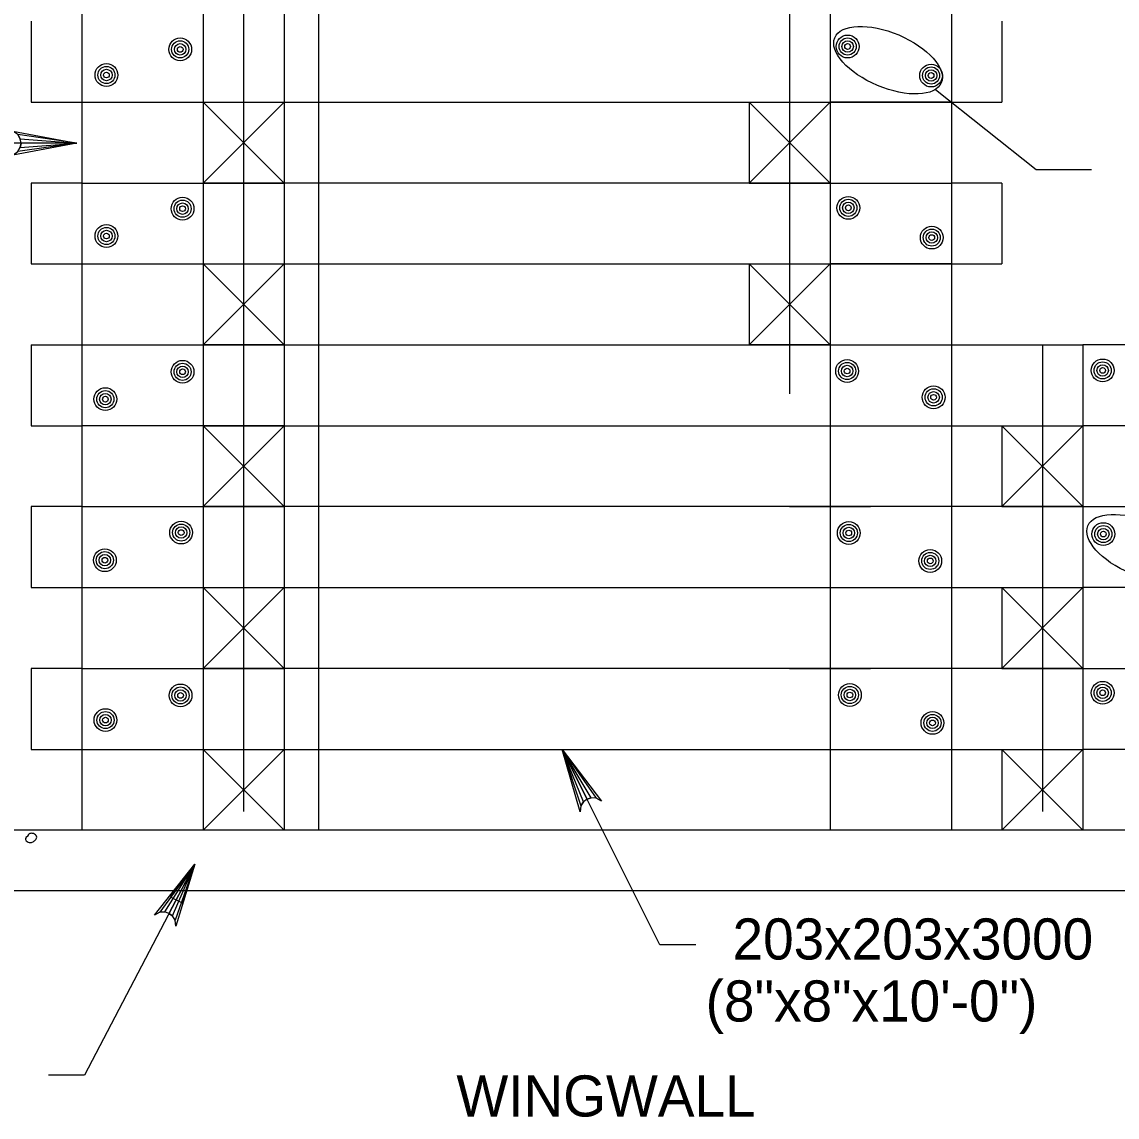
# Model space of a CAD drawing. Extents: x 0 to 36.3, y -44 to 0.
# Drawn here: x 18.454 to 21.652, y -17.836 to -14.638 of the extents above; entities that cross this region are included whole.
import ezdxf

# ---------------------------------------------------------------- set-up
doc = ezdxf.new("R2010")
doc.units = 0
doc.layers.add('3', color=7, linetype='Continuous')
doc.layers.add('5', color=7, linetype='Continuous')

msp = doc.modelspace()

# ---------------------------------------------------------------- linework, layer by layer
at = {"layer": '3'}
for p, q in [((18.6286, -13.9278), (18.6286, -16.9987)), ((19.101, -13.9278), (19.101, -16.9439)), ((19.2192, -13.9278), (19.2192, -16.9987)), ((19.3198, -13.9278), (19.3198, -16.5576)), ((18.9829, -14.1641), (18.9829, -16.9987)), ((20.6955, -14.1641), (20.6955, -15.7248)), ((20.8137, -14.1641), (20.8137, -16.563)), ((21.168, -14.1641), (21.168, -15.8176)), ((21.168, -14.4002), (21.168, -16.9987)), ((18.4809, -14.6365), (18.4809, -14.8727)), ((21.3156, -14.6365), (21.3156, -14.8727)), ((18.4809, -14.8727), (18.6286, -14.8727)), ((18.6286, -14.8727), (18.9829, -14.8727)), ((18.9829, -14.8727), (20.8137, -14.8727)), ((18.9829, -14.8727), (19.2192, -14.8727)), ((18.9829, -14.8727), (18.9829, -15.1089)), ((18.9829, -15.1089), (19.2192, -14.8727)), ((18.9829, -14.8727), (19.2192, -15.1089)), ((19.2192, -14.8727), (19.2192, -15.1089)), ((20.5774, -14.8727), (20.8137, -14.8727)), ((20.5774, -14.8727), (20.8137, -15.1089)), ((20.5774, -15.1089), (20.8137, -14.8727)), ((20.5774, -14.8727), (20.5774, -15.1089)), ((20.8137, -14.8727), (21.168, -14.8727)), ((20.8137, -14.8727), (20.8137, -15.1089)), ((21.168, -14.8727), (20.8137, -14.8727)), ((21.168, -14.8727), (21.3156, -14.8727)), ((18.6286, -15.1089), (18.4809, -15.1089)), ((18.4809, -15.1089), (18.4809, -15.3452)), ((18.6286, -15.1089), (18.9829, -15.1089)), ((18.9829, -15.1089), (19.2192, -15.1089)), ((19.2192, -15.1089), (18.9829, -15.1089)), ((20.8137, -15.1089), (18.9829, -15.1089)), ((20.5774, -15.1089), (20.8137, -15.1089)), ((20.8137, -15.1089), (21.168, -15.1089)), ((21.3156, -15.1089), (21.168, -15.1089)), ((21.3156, -15.1089), (21.3156, -15.3452)), ((18.4809, -15.3452), (18.6286, -15.3452)), ((18.6286, -15.3452), (18.9829, -15.3452)), ((18.9829, -15.3452), (20.8137, -15.3452)), ((18.9829, -15.3452), (19.2192, -15.3452)), ((18.9829, -15.3452), (19.2192, -15.5814)), ((18.9829, -15.5814), (19.2192, -15.3452)), ((18.9829, -15.3452), (18.9829, -15.5814)), ((19.2192, -15.3452), (19.2192, -15.5814)), ((20.5774, -15.3452), (20.8137, -15.3452)), ((20.5774, -15.3452), (20.5774, -15.5814)), ((20.5774, -15.5814), (20.8137, -15.3452)), ((20.5774, -15.3452), (20.8137, -15.5814)), ((20.8137, -15.3452), (20.8137, -15.5814)), ((20.8137, -15.3452), (21.168, -15.3452)), ((21.168, -15.3452), (20.8137, -15.3452)), ((21.168, -15.3452), (21.3156, -15.3452)), ((18.4809, -15.5814), (18.4809, -15.8176)), ((18.4809, -15.5814), (18.6286, -15.5814)), ((18.6286, -15.5814), (18.9829, -15.5814)), ((18.9829, -15.5814), (21.5518, -15.5814)), ((19.2192, -15.5814), (18.9829, -15.5814)), ((18.9829, -15.5814), (19.2192, -15.5814)), ((20.5774, -15.5814), (20.8137, -15.5814)), ((20.8137, -15.5814), (20.5774, -15.5814)), ((21.4337, -15.5814), (21.4337, -16.9439)), ((21.5518, -15.5814), (21.5518, -16.9987)), ((21.9062, -15.5814), (21.5518, -15.5814)), ((18.4809, -15.8176), (18.6286, -15.8176)), ((19.2192, -15.8176), (18.6286, -15.8176)), ((18.9829, -15.8176), (19.2192, -15.8176)), ((18.9829, -15.8176), (18.9829, -16.0538)), ((18.9829, -16.0538), (19.2192, -15.8176)), ((18.9829, -15.8176), (19.2192, -16.0538)), ((19.2192, -15.8176), (19.2192, -16.0538)), ((19.2192, -15.8176), (21.5518, -15.8176)), ((20.6955, -15.8176), (20.9318, -15.8176)), ((21.3156, -15.8176), (21.3156, -16.0538)), ((21.3156, -16.0538), (21.5518, -15.8176)), ((21.3156, -15.8176), (21.5518, -16.0538)), ((21.3156, -15.8176), (21.5518, -15.8176)), ((21.5518, -15.8176), (21.5518, -16.0538)), ((21.9062, -15.8176), (21.5518, -15.8176)), ((18.6286, -16.0538), (18.4809, -16.0538)), ((18.4809, -16.0538), (18.4809, -16.29)), ((18.6286, -16.0538), (18.9829, -16.0538)), ((18.9829, -16.0538), (19.2192, -16.0538)), ((21.5518, -16.0538), (18.9829, -16.0538)), ((20.6955, -16.0538), (20.9318, -16.0538)), ((21.3156, -16.0538), (21.5518, -16.0538)), ((21.5518, -16.0538), (21.9062, -16.0538)), ((18.4809, -16.29), (18.6286, -16.29)), ((18.6286, -16.29), (18.9829, -16.29)), ((18.9829, -16.29), (19.2192, -16.29)), ((18.9829, -16.29), (19.2192, -16.5263)), ((18.9829, -16.5263), (19.2192, -16.29)), ((18.9829, -16.29), (18.9829, -16.5263)), ((18.9829, -16.29), (21.5518, -16.29)), ((19.2192, -16.29), (19.2192, -16.5263)), ((20.6955, -16.29), (20.8137, -16.29)), ((21.3156, -16.29), (21.5518, -16.29)), ((21.3156, -16.29), (21.5518, -16.5263)), ((21.3156, -16.5263), (21.5518, -16.29)), ((21.3156, -16.29), (21.3156, -16.5263)), ((21.5518, -16.29), (21.5518, -16.5263)), ((21.9062, -16.29), (21.5518, -16.29)), ((18.4809, -16.5263), (18.4809, -16.7625)), ((18.6286, -16.5263), (18.4809, -16.5263)), ((18.6286, -16.5263), (18.9829, -16.5263)), ((18.9829, -16.5263), (19.2192, -16.5263)), ((21.5518, -16.5263), (18.9829, -16.5263)), ((20.6955, -16.5263), (20.9318, -16.5263)), ((21.3156, -16.5263), (21.5518, -16.5263)), ((21.5518, -16.5263), (21.9062, -16.5263)), ((19.3198, -16.5576), (19.3198, -16.9987)), ((20.8137, -16.563), (20.8137, -16.9987)), ((18.4809, -16.7625), (18.6286, -16.7625)), ((18.6286, -16.7625), (18.9829, -16.7625)), ((18.9829, -16.7625), (19.2192, -16.7625)), ((18.9829, -16.7625), (21.5518, -16.7625)), ((18.9829, -16.7625), (18.9829, -16.9987)), ((18.9829, -16.9987), (19.2192, -16.7625)), ((18.9829, -16.7625), (19.2192, -16.9987)), ((19.2192, -16.7625), (19.2192, -16.9987)), ((19.5439, -16.7625), (21.4632, -16.7625)), ((21.3156, -16.7625), (21.3156, -16.9987)), ((21.3156, -16.9987), (21.5518, -16.7625)), ((21.3156, -16.7625), (21.5518, -16.9987)), ((21.3156, -16.7625), (21.5518, -16.7625)), ((21.5518, -16.7625), (21.5518, -16.9987)), ((21.9062, -16.7625), (21.5518, -16.7625)), ((22.2309, -16.9987), (18.2742, -16.9987)), ((22.7392, -17.1758), (17.728, -17.1758))]:
    msp.add_line(p, q, dxfattribs=at)
for centre, radius in [((20.865, -14.7102), 0.0333), ((18.916, -14.7186), 0.0333), ((18.916, -14.7186), 0.025), ((18.916, -14.7186), 0.0167), ((18.916, -14.7186), 0.00833), ((20.865, -14.7102), 0.025), ((20.865, -14.7102), 0.0167), ((20.865, -14.7102), 0.00833), ((18.7006, -14.7935), 0.0333), ((18.7006, -14.7935), 0.025), ((21.1087, -14.7949), 0.0333), ((21.1087, -14.7949), 0.025), ((18.7006, -14.7935), 0.0167), ((18.7006, -14.7935), 0.00833), ((21.1087, -14.7949), 0.0167), ((21.1087, -14.7949), 0.00833), ((18.923, -15.1837), 0.0333), ((18.923, -15.1837), 0.025), ((20.8671, -15.1813), 0.0333), ((20.8671, -15.1813), 0.025), ((18.923, -15.1837), 0.0167), ((18.923, -15.1837), 0.00833), ((20.8671, -15.1813), 0.0167), ((20.8671, -15.1813), 0.00833), ((18.7006, -15.2636), 0.0333), ((18.7006, -15.2636), 0.025), ((18.7006, -15.2636), 0.0167), ((21.1107, -15.2681), 0.0333), ((21.1107, -15.2681), 0.025), ((21.1107, -15.2681), 0.0167), ((18.7006, -15.2636), 0.00833), ((21.1107, -15.2681), 0.00833), ((18.923, -15.66), 0.0333), ((18.923, -15.66), 0.025), ((20.8635, -15.6578), 0.0333), ((20.8635, -15.6578), 0.025), ((21.6097, -15.656), 0.0333), ((21.6097, -15.656), 0.025), ((18.923, -15.66), 0.0167), ((18.923, -15.66), 0.00833), ((20.8635, -15.6578), 0.0167), ((20.8635, -15.6578), 0.00833), ((21.6097, -15.656), 0.0167), ((21.6097, -15.656), 0.00833), ((21.1161, -15.7345), 0.0333), ((18.6975, -15.7399), 0.0333), ((18.6975, -15.7399), 0.025), ((18.6975, -15.7399), 0.0167), ((18.6975, -15.7399), 0.00833), ((21.1161, -15.7345), 0.025), ((21.1161, -15.7345), 0.0167), ((21.1161, -15.7345), 0.00833), ((18.9188, -16.1295), 0.0333), ((18.9188, -16.1295), 0.025), ((18.9188, -16.1295), 0.0167), ((20.8684, -16.1307), 0.0333), ((20.8684, -16.1307), 0.025), ((20.8684, -16.1307), 0.0167), ((21.6118, -16.1339), 0.0333), ((21.6118, -16.1339), 0.025), ((21.6118, -16.1339), 0.0167), ((18.9188, -16.1295), 0.00833), ((20.8684, -16.1307), 0.00833), ((21.6118, -16.1339), 0.00833), ((18.6961, -16.2102), 0.0333), ((21.1063, -16.2123), 0.0333), ((18.6961, -16.2102), 0.025), ((18.6961, -16.2102), 0.0167), ((18.6961, -16.2102), 0.00833), ((21.1063, -16.2123), 0.025), ((21.1063, -16.2123), 0.0167), ((21.1063, -16.2123), 0.00833), ((21.6097, -16.5973), 0.0333), ((18.917, -16.605), 0.0333), ((18.917, -16.605), 0.025), ((18.917, -16.605), 0.0167), ((18.917, -16.605), 0.00833), ((20.8716, -16.6037), 0.0333), ((20.8716, -16.6037), 0.025), ((20.8716, -16.6037), 0.0167), ((20.8716, -16.6037), 0.00833), ((21.6097, -16.5973), 0.025), ((21.6097, -16.5973), 0.0167), ((21.6097, -16.5973), 0.00833), ((18.6978, -16.677), 0.0333), ((18.6978, -16.677), 0.025), ((18.6978, -16.677), 0.0167), ((21.1128, -16.6852), 0.0333), ((21.1128, -16.6852), 0.025), ((18.6978, -16.677), 0.00833), ((21.1128, -16.6852), 0.0167), ((21.1128, -16.6852), 0.00833)]:
    msp.add_circle(centre, radius, dxfattribs=at)
for centre, radius, start, end in [((18.4836, -17.0203), 0.014, 140.7081, 167.2711), ((18.4804, -17.0176), 0.00984, 108.9149, 140.7081), ((18.4822, -17.023), 0.0155, 90, 108.9149), ((18.4822, -17.0257), 0.0182, 72.5511, 90), ((18.4831, -17.0229), 0.0153, 47.7288, 72.5511), ((18.4856, -17.0202), 0.0115, 19.08, 47.7288), ((18.4718, -17.0242), 0.00747, 143.9702, 187.7584), ((18.4715, -17.0243), 0.00724, 187.7584, 225.0025), ((18.473, -17.0252), 0.00907, 104.4085, 143.9702), ((18.4787, -17.0171), 0.0173, 225.0025, 248.8171), ((18.4782, -17.0183), 0.0161, 248.8171, 282.2637), ((18.4773, -17.0141), 0.0203, 282.2637, 311.9318), ((18.4763, -17.013), 0.0219, 311.9318, 336.3688), ((18.4896, -17.0188), 0.00738, 336.3688, 19.08)]:
    msp.add_arc(centre, radius, start, end, dxfattribs=at)
at = {"layer": '5'}
for p, q in [((21.1212, -14.8355), (21.4152, -15.0691)), ((21.4152, -15.0691), (21.5768, -15.0691)), ((20.3167, -17.3329), (20.0313, -16.7625)), ((18.9586, -17.0972), (18.6363, -17.7138)), ((20.4213, -17.3329), (20.3167, -17.3329)), ((18.6363, -17.7138), (18.5316, -17.7138))]:
    msp.add_line(p, q, dxfattribs=at)
for points in [[(18.6138, -14.9923), (18.4274, -15.0272), (18.4417, -15.0172), (18.4492, -15.0047), (18.4513, -14.9923), (18.4492, -14.9797), (18.4417, -14.9672), (18.4274, -14.9573), (18.6138, -14.9923), (18.4417, -14.9672), (18.4492, -14.9797), (18.6138, -14.9923), (18.4513, -14.9923), (18.4492, -15.0047), (18.6138, -14.9923), (18.4417, -15.0172)], [(18.6138, -14.9922), (17.9997, -14.9922)], [(20.0313, -16.7625), (20.146, -16.9136), (20.1307, -16.9052), (20.1162, -16.9042), (20.104, -16.9078), (20.0938, -16.9153), (20.0859, -16.9276), (20.0835, -16.9448), (20.0313, -16.7625), (20.0859, -16.9276), (20.0938, -16.9153), (20.0313, -16.7625), (20.104, -16.9078), (20.1162, -16.9042), (20.0313, -16.7625), (20.1307, -16.9052)], [(18.9586, -17.0972), (18.9032, -17.2787), (18.901, -17.2613), (18.8934, -17.2489), (18.8833, -17.2413), (18.8712, -17.2373), (18.8567, -17.2382), (18.8412, -17.2462), (18.9586, -17.0972), (18.8567, -17.2382), (18.8712, -17.2373), (18.9586, -17.0972), (18.8833, -17.2413), (18.8934, -17.2489), (18.9586, -17.0972), (18.901, -17.2613)]]:
    msp.add_lwpolyline(points, dxfattribs=at)
msp.add_lwpolyline([(18.8864, -17.1928), (18.9213, -17.211), (18.9586, -17.0972)], close=True, dxfattribs=at)
for centre in [(20.983, -14.7502), (21.7222, -16.1751)]:
    msp.add_ellipse(centre, major_axis=(-0.1556, 0.0657), ratio=0.473013, dxfattribs=at)

# ---------------------------------------------------------------- texts
for s, p in [('203x203x3000', (20.529, -17.3761)), ('(8"x8"x10\'-0")', (20.4505, -17.5571)), ('WINGWALL', (19.7226, -17.8345))]:
    msp.add_text(s, height=0.12, dxfattribs=at).set_placement(p)

doc.saveas('drawing.dxf')
